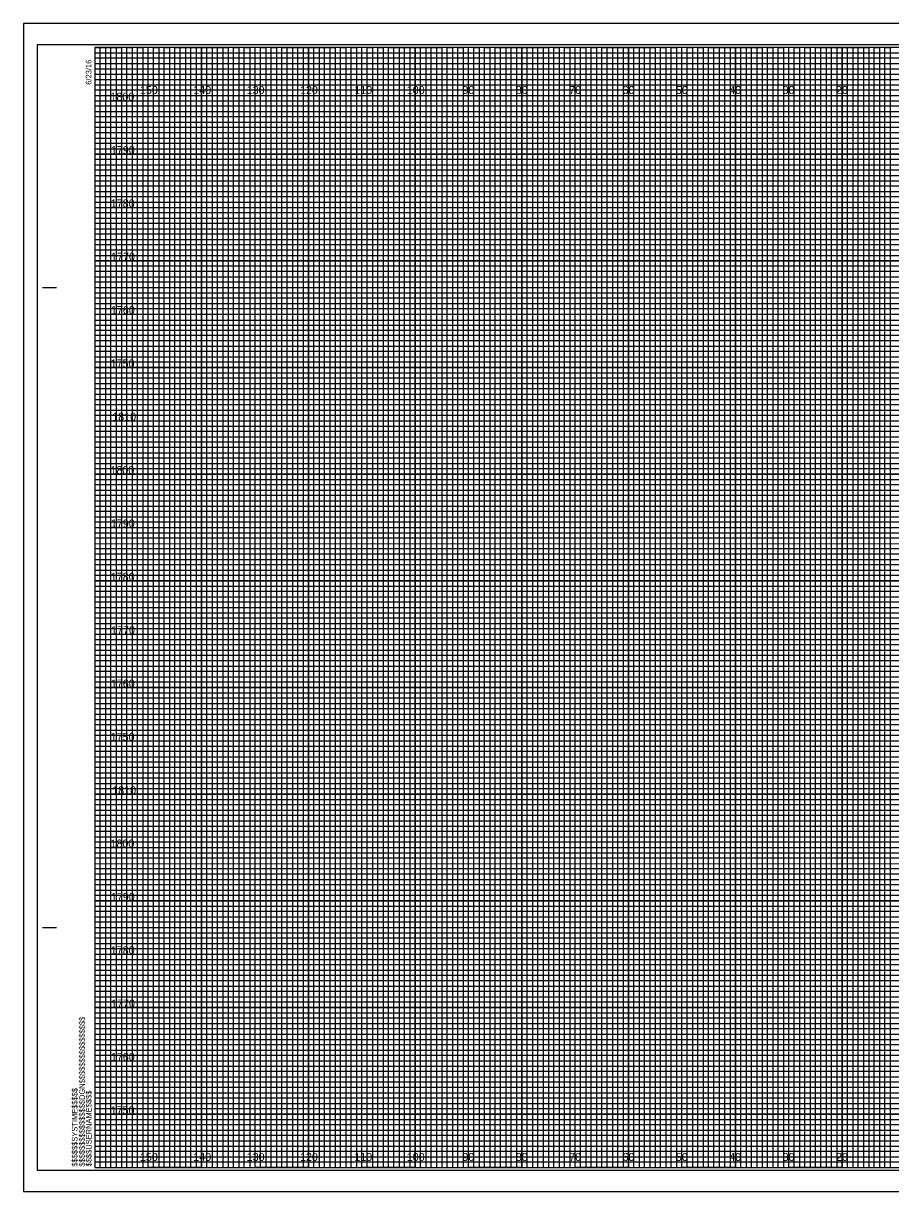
# Model space of a CAD drawing. Extents: x -15 to 323, y -5 to 6170.
# Drawn here: x -13.4 to 149.1, y 2415.5 to 2634.5 of the extents above; entities that cross this region are included whole.
import ezdxf

# ---------------------------------------------------------------- set-up
doc = ezdxf.new("R2010")
doc.units = 0
for name, color, linetype in [('Prop XS DDE', 7, 'Continuous'), ('Prop XS DDE Slope Text', 7, 'Continuous'), ('Prop XS DDE Text', 7, 'Continuous'), ('Prop XS Earthwork Shape', 7, 'Continuous'), ('Prop XS Noise Wall', 7, 'Continuous'), ('Prop XS Retaining Wall', 7, 'Continuous'), ('Prop XS Station Labels', 7, 'Continuous'), ('Scratch_Level_3', 7, 'Continuous'), ('Scratch_Level_7', 7, 'Continuous'), ('Scratch_Level_8', 7, 'Continuous'), ('Sheet Cross Section Grid Minor 1 CELL', 7, 'Continuous')]:
    doc.layers.add(name, color=color, linetype=linetype)

msp = doc.modelspace()

# ---------------------------------------------------------------- linework, layer by layer
at = {"layer": 'Prop XS DDE'}
msp.add_lwpolyline([(-13.4, 2415.5), (323.3, 2415.5), (323.3, 2634.5), (-13.4, 2634.5)], close=True, dxfattribs=at)
at = {"layer": 'Prop XS DDE Slope Text'}
msp.add_lwpolyline([(-10.8, 2419.5), (322.4, 2419.5), (322.4, 2630.5), (-10.8, 2630.5)], close=True, dxfattribs=at)
at = {"layer": 'Prop XS DDE Text'}
for p, q in [((10, 2420), (10, 2630)), ((20, 2420), (20, 2630)), ((30, 2420), (30, 2630)), ((40, 2420), (40, 2630)), ((50, 2420), (50, 2630)), ((60, 2420), (60, 2630)), ((70, 2420), (70, 2630)), ((80, 2420), (80, 2630)), ((90, 2420), (90, 2630)), ((100, 2420), (100, 2630)), ((110, 2420), (110, 2630)), ((120, 2420), (120, 2630)), ((130, 2420), (130, 2630)), ((140, 2420), (140, 2630)), ((0, 2620), (320, 2620)), ((0, 2610), (320, 2610)), ((0, 2600), (320, 2600)), ((0, 2590), (320, 2590)), ((0, 2580), (320, 2580)), ((0, 2570), (320, 2570)), ((0, 2560), (320, 2560)), ((0, 2550), (320, 2550)), ((0, 2540), (320, 2540)), ((0, 2530), (320, 2530)), ((0, 2520), (320, 2520)), ((0, 2510), (320, 2510)), ((0, 2500), (320, 2500)), ((0, 2490), (320, 2490)), ((0, 2480), (320, 2480)), ((0, 2470), (320, 2470)), ((0, 2460), (320, 2460)), ((0, 2450), (320, 2450)), ((0, 2440), (320, 2440)), ((0, 2430), (320, 2430))]:
    msp.add_line(p, q, dxfattribs=at)
at = {"layer": 'Prop XS Earthwork Shape'}
for p, q in [((10, 2630), (0, 2630)), ((10, 2420), (10, 2630)), ((30, 2630), (20, 2630)), ((20, 2630), (20, 2420)), ((30, 2420), (30, 2630)), ((50, 2630), (40, 2630)), ((40, 2630), (40, 2420)), ((50, 2420), (50, 2630)), ((70, 2630), (60, 2630)), ((60, 2630), (60, 2420)), ((70, 2420), (70, 2630)), ((90, 2630), (80, 2630)), ((80, 2630), (80, 2420)), ((90, 2420), (90, 2630)), ((110, 2630), (100, 2630)), ((100, 2630), (100, 2420)), ((110, 2420), (110, 2630)), ((130, 2630), (120, 2630)), ((120, 2630), (120, 2420)), ((130, 2420), (130, 2630)), ((150, 2630), (140, 2630)), ((140, 2630), (140, 2420)), ((20, 2420), (10, 2420)), ((40, 2420), (30, 2420)), ((60, 2420), (50, 2420)), ((80, 2420), (70, 2420)), ((100, 2420), (90, 2420)), ((120, 2420), (110, 2420)), ((140, 2420), (130, 2420))]:
    msp.add_line(p, q, dxfattribs=at)
for points in [[(0, 2620), (320, 2620), (320, 2610), (0, 2610)], [(0, 2600), (320, 2600), (320, 2590), (0, 2590)], [(0, 2580), (320, 2580), (320, 2570), (0, 2570)], [(0, 2560), (320, 2560), (320, 2550), (0, 2550)], [(0, 2540), (320, 2540), (320, 2530), (0, 2530)], [(0, 2520), (320, 2520), (320, 2510), (0, 2510)], [(0, 2500), (320, 2500), (320, 2490), (0, 2490)], [(0, 2480), (320, 2480), (320, 2470), (0, 2470)], [(0, 2460), (320, 2460), (320, 2450), (0, 2450)], [(0, 2440), (320, 2440), (320, 2430), (0, 2430)]]:
    msp.add_lwpolyline(points, dxfattribs=at)
at = {"layer": 'Prop XS Noise Wall'}
for p, q in [((-9.8, 2585), (-7.3, 2585)), ((-9.7, 2585), (-7.2, 2585)), ((-9.8, 2465), (-7.3, 2465)), ((-9.7, 2465), (-7.2, 2465)), ((0, 2420), (0, 2420)), ((0, 2420), (0, 2420)), ((0, 2420), (0, 2420)), ((0, 2420), (0, 2420)), ((0, 2420), (0, 2420)), ((0, 2420), (0, 2420)), ((0, 2420), (0, 2420))]:
    msp.add_line(p, q, dxfattribs=at)
msp.add_lwpolyline([(320, 2630), (0, 2630), (0, 2420), (320, 2420)], close=True, dxfattribs=at)
at = {"layer": 'Prop XS Retaining Wall'}
for points in [[(0, 2420), (1, 2420), (1, 2630), (2, 2630), (2, 2420)], [(2, 2420), (3, 2420), (3, 2630), (4, 2630), (4, 2420)], [(5, 2420), (6, 2420), (6, 2630), (7, 2630), (7, 2420)], [(7, 2420), (8, 2420), (8, 2630), (9, 2630), (9, 2420)], [(10, 2420), (11, 2420), (11, 2630), (12, 2630), (12, 2420)], [(12, 2420), (13, 2420), (13, 2630), (14, 2630), (14, 2420)], [(15, 2420), (16, 2420), (16, 2630), (17, 2630), (17, 2420)], [(17, 2420), (18, 2420), (18, 2630), (19, 2630), (19, 2420)], [(20, 2420), (21, 2420), (21, 2630), (22, 2630), (22, 2420)], [(22, 2420), (23, 2420), (23, 2630), (24, 2630), (24, 2420)], [(25, 2420), (26, 2420), (26, 2630), (27, 2630), (27, 2420)], [(27, 2420), (28, 2420), (28, 2630), (29, 2630), (29, 2420)], [(30, 2420), (31, 2420), (31, 2630), (32, 2630), (32, 2420)], [(32, 2420), (33, 2420), (33, 2630), (34, 2630), (34, 2420)], [(35, 2420), (36, 2420), (36, 2630), (37, 2630), (37, 2420)], [(37, 2420), (38, 2420), (38, 2630), (39, 2630), (39, 2420)], [(40, 2420), (41, 2420), (41, 2630), (42, 2630), (42, 2420)], [(42, 2420), (43, 2420), (43, 2630), (44, 2630), (44, 2420)], [(45, 2420), (46, 2420), (46, 2630), (47, 2630), (47, 2420)], [(47, 2420), (48, 2420), (48, 2630), (49, 2630), (49, 2420)], [(50, 2420), (51, 2420), (51, 2630), (52, 2630), (52, 2420)], [(52, 2420), (53, 2420), (53, 2630), (54, 2630), (54, 2420)], [(55, 2420), (56, 2420), (56, 2630), (57, 2630), (57, 2420)], [(57, 2420), (58, 2420), (58, 2630), (59, 2630), (59, 2420)], [(60, 2420), (61, 2420), (61, 2630), (62, 2630), (62, 2420)], [(62, 2420), (63, 2420), (63, 2630), (64, 2630), (64, 2420)], [(65, 2420), (66, 2420), (66, 2630), (67, 2630), (67, 2420)], [(67, 2420), (68, 2420), (68, 2630), (69, 2630), (69, 2420)], [(70, 2420), (71, 2420), (71, 2630), (72, 2630), (72, 2420)], [(72, 2420), (73, 2420), (73, 2630), (74, 2630), (74, 2420)], [(75, 2420), (76, 2420), (76, 2630), (77, 2630), (77, 2420)], [(77, 2420), (78, 2420), (78, 2630), (79, 2630), (79, 2420)], [(80, 2420), (81, 2420), (81, 2630), (82, 2630), (82, 2420)], [(82, 2420), (83, 2420), (83, 2630), (84, 2630), (84, 2420)], [(85, 2420), (86, 2420), (86, 2630), (87, 2630), (87, 2420)], [(87, 2420), (88, 2420), (88, 2630), (89, 2630), (89, 2420)], [(90, 2420), (91, 2420), (91, 2630), (92, 2630), (92, 2420)], [(92, 2420), (93, 2420), (93, 2630), (94, 2630), (94, 2420)], [(95, 2420), (96, 2420), (96, 2630), (97, 2630), (97, 2420)], [(97, 2420), (98, 2420), (98, 2630), (99, 2630), (99, 2420)], [(100, 2420), (101, 2420), (101, 2630), (102, 2630), (102, 2420)], [(102, 2420), (103, 2420), (103, 2630), (104, 2630), (104, 2420)], [(105, 2420), (106, 2420), (106, 2630), (107, 2630), (107, 2420)], [(107, 2420), (108, 2420), (108, 2630), (109, 2630), (109, 2420)], [(110, 2420), (111, 2420), (111, 2630), (112, 2630), (112, 2420)], [(112, 2420), (113, 2420), (113, 2630), (114, 2630), (114, 2420)], [(115, 2420), (116, 2420), (116, 2630), (117, 2630), (117, 2420)], [(117, 2420), (118, 2420), (118, 2630), (119, 2630), (119, 2420)], [(120, 2420), (121, 2420), (121, 2630), (122, 2630), (122, 2420)], [(122, 2420), (123, 2420), (123, 2630), (124, 2630), (124, 2420)], [(125, 2420), (126, 2420), (126, 2630), (127, 2630), (127, 2420)], [(127, 2420), (128, 2420), (128, 2630), (129, 2630), (129, 2420)], [(130, 2420), (131, 2420), (131, 2630), (132, 2630), (132, 2420)], [(132, 2420), (133, 2420), (133, 2630), (134, 2630), (134, 2420)], [(135, 2420), (136, 2420), (136, 2630), (137, 2630), (137, 2420)], [(137, 2420), (138, 2420), (138, 2630), (139, 2630), (139, 2420)], [(140, 2420), (141, 2420), (141, 2630), (142, 2630), (142, 2420)], [(142, 2420), (143, 2420), (143, 2630), (144, 2630), (144, 2420)], [(145, 2420), (146, 2420), (146, 2630), (147, 2630), (147, 2420)], [(147, 2420), (148, 2420), (148, 2630), (149, 2630), (149, 2420)]]:
    msp.add_lwpolyline(points, dxfattribs=at)
at = {"layer": 'Prop XS Station Labels'}
for points in [[(0, 2630), (5, 2630), (5, 2420), (15, 2420), (15, 2630), (25, 2630), (25, 2420), (35, 2420), (35, 2630), (45, 2630), (45, 2420), (55, 2420), (55, 2630), (65, 2630), (65, 2420), (75, 2420), (75, 2630), (85, 2630), (85, 2420), (95, 2420), (95, 2630), (105, 2630), (105, 2420), (115, 2420), (115, 2630), (125, 2630), (125, 2420), (135, 2420), (135, 2630), (145, 2630), (145, 2420), (155, 2420)], [(0, 2625), (275, 2625)], [(0, 2605), (320, 2605), (320, 2615), (0, 2615)], [(0, 2585), (320, 2585), (320, 2595), (0, 2595)], [(0, 2565), (320, 2565), (320, 2575), (0, 2575)], [(0, 2545), (320, 2545), (320, 2555), (0, 2555)], [(0, 2525), (320, 2525), (320, 2535), (0, 2535)], [(0, 2505), (320, 2505), (320, 2515), (0, 2515)], [(0, 2485), (320, 2485), (320, 2495), (0, 2495)], [(0, 2465), (320, 2465), (320, 2475), (0, 2475)], [(0, 2445), (320, 2445), (320, 2455), (0, 2455)], [(0, 2425), (320, 2425), (320, 2435), (0, 2435)]]:
    msp.add_lwpolyline(points, dxfattribs=at)
at = {"layer": 'Scratch_Level_7'}
for p, q in [((323.3, 2634.5), (-13.4, 2634.5)), ((-13.4, 2634.5), (-13.4, 2415.5)), ((-13.4, 2415.5), (323.3, 2415.5))]:
    msp.add_line(p, q, dxfattribs=at)
at = {"layer": 'Sheet Cross Section Grid Minor 1 CELL'}
for p, q in [((0, 2629), (260, 2629)), ((260, 2627.98), (0, 2627.98)), ((0, 2627.98), (0, 2627)), ((0, 2627), (260, 2627)), ((260, 2625.89), (0, 2625.89)), ((0, 2625.89), (0, 2624)), ((0, 2624), (320, 2624))]:
    msp.add_line(p, q, dxfattribs=at)
for points in [[(0, 2623), (270, 2623), (320, 2623), (320, 2622), (0, 2622)], [(0, 2621), (320, 2621), (320, 2619), (0, 2619)], [(0, 2618), (320, 2618), (320, 2617), (0, 2616.98)], [(0, 2616), (320, 2616), (320, 2614), (0, 2614)], [(0, 2613), (320, 2613), (320, 2612), (0, 2612)], [(0, 2611), (320, 2611), (320, 2609), (0, 2609)], [(0, 2608), (320, 2608), (320, 2607), (0, 2607)], [(0, 2606), (320, 2606), (320, 2604), (0, 2604)], [(0, 2603), (320, 2603), (320, 2602), (0, 2602)], [(0, 2601), (320, 2601), (320, 2599), (0, 2599)], [(0, 2598), (320, 2598), (320, 2597), (0, 2597)], [(0, 2596), (320, 2596), (320, 2593.95), (320, 2593), (320, 2592), (0, 2592)], [(0, 2594), (320, 2594), (320, 2593), (0, 2593)], [(0, 2591), (320, 2591), (320, 2589), (0, 2589.03)], [(0, 2589.03), (320, 2589), (320, 2588), (0, 2588)], [(0, 2587), (320, 2587), (320, 2586), (0, 2586)], [(0, 2584), (320, 2584), (320, 2583), (0, 2583)], [(0, 2582), (320, 2582), (320, 2581), (0, 2581)], [(-0.07, 2578.89), (320, 2578.89), (320, 2577.88), (-0.07, 2577.88)], [(0, 2577), (320, 2577), (320, 2576), (0, 2576)], [(0, 2574), (320, 2574), (320, 2573), (0, 2573)], [(0, 2572), (320, 2572), (320, 2571), (0, 2571)], [(0, 2569), (320, 2569), (320, 2568), (0, 2568)], [(0, 2567), (320, 2567), (320, 2566), (0, 2566)], [(0, 2564), (320, 2564), (320, 2563), (0, 2563)], [(0, 2562), (320, 2562), (320, 2561), (0, 2561)], [(0, 2559), (320, 2559), (319.99, 2557.98), (0, 2558)], [(0, 2557), (320, 2557), (320, 2556), (0, 2556)], [(0, 2554), (320, 2554), (320, 2553), (0, 2553)], [(0, 2552), (320, 2552), (320, 2551), (0, 2551)], [(0, 2549), (320, 2549), (320, 2548), (0, 2548)], [(0, 2547), (320, 2547), (320, 2546), (0, 2546)], [(0, 2544), (320, 2544), (320, 2543), (0, 2543)], [(0, 2542), (320, 2542), (320, 2541), (0, 2541)], [(0, 2539), (320, 2539), (320, 2538), (0, 2538)], [(0, 2536.99), (320.07, 2536.91), (320, 2536), (0, 2536)], [(0, 2534), (320, 2534), (320, 2533), (0, 2533)], [(0, 2532), (320, 2532), (320, 2531), (0, 2531)], [(0, 2529), (320, 2529), (320, 2528), (0, 2528)], [(0, 2527), (320, 2527), (320, 2526), (0, 2526)], [(0, 2524), (320, 2524), (320, 2523), (0, 2523)], [(0, 2522), (320, 2522), (320, 2521), (0, 2521)], [(0, 2519), (320, 2519), (320, 2518), (0, 2518)], [(0, 2517), (320, 2517), (320, 2516), (0, 2516)], [(0, 2514), (320, 2514), (320, 2513), (0, 2513)], [(0, 2512), (320, 2512), (320, 2511), (0, 2511)], [(0, 2509), (320, 2509), (320, 2508), (0, 2508)], [(0, 2507), (320, 2507), (320, 2506), (0, 2506)], [(0, 2504), (320, 2504), (320, 2503), (0, 2503)], [(0, 2502), (320, 2502), (320, 2501), (0, 2501)], [(0, 2499), (320, 2499), (319.99, 2497.98), (0, 2498)], [(0, 2497), (320, 2497), (320, 2496), (0, 2496)], [(0, 2494), (320, 2494), (320, 2493), (0, 2493)], [(0, 2492), (320, 2492), (320, 2491), (0, 2491)], [(0, 2489), (320, 2489), (320, 2488), (0, 2488)], [(0, 2487), (320, 2487), (320, 2486), (0, 2486)], [(0, 2484), (320, 2484), (320, 2483), (0, 2483)], [(0, 2482), (320, 2482), (320, 2481), (0, 2481)], [(0, 2479), (320, 2479), (320, 2478), (0, 2478)], [(0, 2476.99), (320.07, 2476.91), (320, 2476), (0, 2476)], [(0, 2474), (320, 2474), (320, 2473), (0, 2473)], [(0, 2472), (320, 2472), (320, 2471), (0, 2471)], [(0, 2469), (320, 2469), (320, 2468), (0, 2468)], [(0, 2467), (320, 2467), (320, 2466), (0, 2466)], [(0, 2464), (320, 2464), (320, 2463), (0, 2463)], [(0, 2462), (320, 2462), (320, 2461), (0, 2461)], [(0, 2459), (320, 2459), (320, 2458), (0, 2458)], [(0, 2457), (320, 2457), (320, 2456), (0, 2456)], [(0, 2454), (320, 2454), (320, 2453), (0, 2453)], [(0, 2452), (320, 2452), (320, 2451), (0, 2451)], [(0, 2449), (320, 2449), (320, 2448), (0, 2448)], [(0, 2447), (320, 2447), (320, 2446), (0, 2446)], [(0, 2444), (320, 2444), (320, 2443), (0, 2443)], [(0, 2442), (320, 2442), (320, 2441), (0, 2441)], [(0, 2439), (320, 2439), (320, 2438), (0, 2438)], [(0, 2437), (320, 2437), (320, 2436), (0, 2436)], [(0, 2434), (320, 2434), (320, 2433), (0, 2433)], [(0, 2432), (320, 2432), (320, 2431), (0, 2431)], [(0, 2429), (320, 2429), (320, 2428), (0, 2428)], [(0, 2427), (320, 2427), (320, 2426), (0, 2426)], [(0, 2424), (320, 2424), (320, 2423), (0, 2423)], [(0, 2422), (320, 2422), (320, 2421), (0, 2421)]]:
    msp.add_lwpolyline(points, dxfattribs=at)

# ---------------------------------------------------------------- texts
at = {"layer": 'Prop XS Noise Wall'}
for s, p in [('6/23/16', (-0.65, 2623)), ('$$$$$$$$$$$$$$$$DGN$$$$$$$$$$$$$$$$', (-1.88, 2420.18)), ('$$$$$$SYSTIME$$$$$', (-3.26, 2420.18)), ('$$$$USERNAME$$$$', (-0.62, 2420.23))]:
    msp.add_text(s, height=1.05, rotation=90, dxfattribs=at).set_placement(p)
at = {"layer": 'Scratch_Level_3'}
for s, p in [('1800', (2.92, 2620)), ('1790', (3, 2610)), ('1780', (2.98, 2600)), ('1770', (3.04, 2590)), ('1760', (3, 2580)), ('1750', (2.96, 2570)), ('1810', (3.25, 2560)), ('1800', (2.92, 2550)), ('1790', (3, 2540)), ('1780', (2.98, 2530)), ('1770', (3.04, 2520)), ('1760', (3, 2510)), ('1750', (2.96, 2500)), ('1810', (3.25, 2490)), ('1800', (2.92, 2480)), ('1790', (3, 2470)), ('1780', (2.98, 2460)), ('1770', (3.04, 2450)), ('1760', (3, 2440)), ('1750', (2.96, 2430))]:
    msp.add_text(s, height=1.5, dxfattribs=at).set_placement(p)
at = {"layer": 'Scratch_Level_8'}
for s, p in [('150', (8.44, 2621.25)), ('140', (18.44, 2621.25)), ('130', (28.44, 2621.25)), ('120', (38.44, 2621.25)), ('110', (48.62, 2621.25)), ('100', (58.44, 2621.25)), ('90', (68.86, 2621.25)), ('80', (78.86, 2621.25)), ('70', (88.86, 2621.25)), ('60', (98.86, 2621.25)), ('50', (108.86, 2621.25)), ('40', (118.86, 2621.25)), ('30', (128.86, 2621.25)), ('20', (138.86, 2621.25)), ('150', (8.44, 2421.25)), ('140', (18.44, 2421.25)), ('130', (28.44, 2421.25)), ('120', (38.44, 2421.25)), ('110', (48.62, 2421.25)), ('100', (58.44, 2421.25)), ('90', (68.86, 2421.25)), ('80', (78.86, 2421.25)), ('70', (88.86, 2421.25)), ('60', (98.86, 2421.25)), ('50', (108.86, 2421.25)), ('40', (118.86, 2421.25)), ('30', (128.86, 2421.25)), ('20', (138.86, 2421.25))]:
    msp.add_text(s, height=1.5, dxfattribs=at).set_placement(p)

doc.saveas('drawing.dxf')
